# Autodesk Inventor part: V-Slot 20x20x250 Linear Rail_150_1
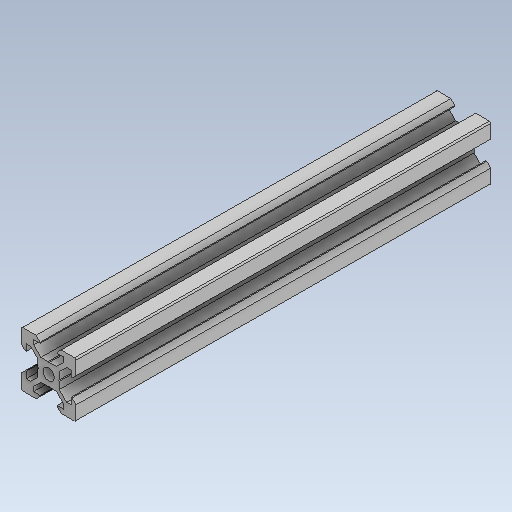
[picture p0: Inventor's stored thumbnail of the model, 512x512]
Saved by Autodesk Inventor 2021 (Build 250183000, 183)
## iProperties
Created: 2026-10
Part Number: V-Slot 20x20x250 Linear Rail_150_1
Material: Steel
Document SubType Name: Modeling
Designer: hp
Density: 7.85 g/cm^3
Appearance: Default
Author: hp
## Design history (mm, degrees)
feature "Body1"
body "Solid1"
